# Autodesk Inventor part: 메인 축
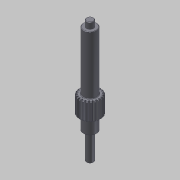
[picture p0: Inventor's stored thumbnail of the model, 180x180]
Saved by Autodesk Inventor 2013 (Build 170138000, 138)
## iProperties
Created: 2016-02
Part Number: 메인 축
Material: 강철, 연강
Document SubType Name: Modeling
Categories: <?xml version="1.0" encoding="UTF-16"?> <MemberInstance><Categories><FamilyTemplate><FamilyTemplateParameter ValueType="xs:double" Id="1" ObjectReferenceKey="da
Density: 7.86 g/cm^3
Mass: 187.503 g
Surface Area: 82.0529 cm^2
Volume: 23.8554 cm^3
CustomPartVersion: 1
Author: mdu
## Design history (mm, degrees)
sketch "Sketch1"
  geometry: C1 r 12 at (0, 0)
  constraints: 1 centre point
  dimensions: "d0" = 24 diameter of C1 (= da_da)
extrude "Extrusion1" new body sketch "Sketch1" distance "d1" = 20 (= da_b); taper "d2" = 0 deg
workplane "Work Plane2"
feature "피치 지름" dims "d4" = 10, "d5" = 0
workplane "Work Plane8"
workplane "Work Plane9"
chamfer "모따기1" distance "d49" = 1; stored, may be unused: second distance "d50" = 2, angle "d51" = 45 deg
sketch "스케치3"
  geometry: C1 r 7.5 at (0, 0); 1 further point
  constraints: 1 centre point, 1 coincident
  dimensions: "d52" = 15 diameter of C1
extrude "돌출2" join sketch "스케치3" distance "d53" = 66; taper "d54" = 0 deg
sketch "스케치4"
  geometry: C1 r 4 at (0, 0); 1 further point
  constraints: 1 centre point, 1 coincident
  dimensions: "d55" = 8 diameter of C1
extrude "돌출3" join sketch "스케치4" distance "d56" = 7; taper "d57" = 0 deg
sketch "스케치5"
  geometry: C1 r 7.5 at (0, 0) reference; C2 r 7.5 at (0, 0) reference; 1 further point
extrude "돌출4" join sketch "스케치5" distance "d62" = 16; taper "d63" = 0 deg
sketch "스케치6"
  geometry: C1 r 4 at (0, 0); 1 further point
  constraints: 1 centre point, 1 coincident
  dimensions: "d64" = 8 diameter of C1
extrude "돌출5" join sketch "스케치6" distance "d65" = 30; taper "d66" = 0 deg
chamfer "모따기2" distance "d58" = 0.5; stored, may be unused: second distance "d59" = 2, angle "d60" = 45 deg
fillet "모깎기1" dims "d61" = 0.5
feature "스퍼 기어" dims "da_b" = 20, "da_d" = 22, "da_aw" = 31, "da_da" = 24, "da_df" = 19.5, "da_dw" = 22, angle "da_beta" = 0 deg, "da_lefttooth" = 0, "da_righttooth" = 0
sketch "스케치7" dims "d68" = 18
  geometry: C1 r 0.25 at (0, -9); 2 further points
  constraints: 2 vertical alignment, 1 centre point, 1 coincident, 2 other
  dimensions: "d67" = 0.5 diameter of C1
extrude "돌출6" join sketch "스케치7" distance "d69" = 0.3; taper "d70" = 0 deg
body "Solid1"
sketch "Sketch2"
  geometry: C1 r 12 at (0, 0) reference; C2 r 11 at (0, 0)
  constraints: 1 centre point, 1 coincident
  dimensions: "d3" = 22 diameter of C2 (= da_dw)
body "Srf1"
node "투영된 루프1"
other parameters: "d16" = 31 (= da_aw), "d17" = 0, "d34" = 1.428 (computed from da_z), "d39" = 0, "d41" = 0, "d43" = 31 (= da_aw), "d46" = 31 (= da_aw), "d47" = 0, "d48" = 0
